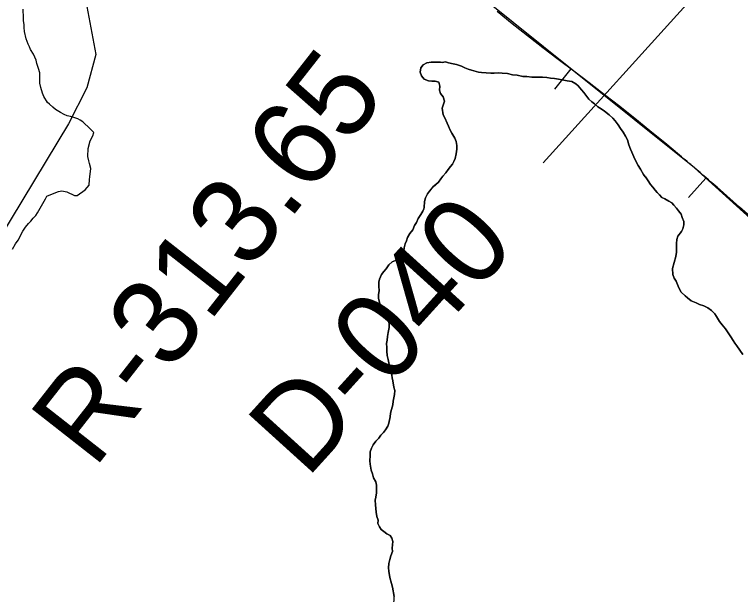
# Model space of a CAD drawing. Extents: x 3180038 to 3217926, y 922069 to 947485.
# Drawn here: x 3193903 to 3194600, y 943842 to 944398 of the extents above; entities that cross this region are included whole.
import ezdxf

# ---------------------------------------------------------------- set-up
doc = ezdxf.new("R2010")
doc.units = 0
for name, color, linetype in [('V-BORW-LINE', 7, 'Continuous'), ('V-RIVR-RANG', 7, 'Continuous'), ('V-RIVR-RANG-IDEN', 7, 'Continuous'), ('V-SITE-VEGE', 7, 'Continuous'), ('V-TOPO-SHOR', 7, 'Continuous')]:
    doc.layers.add(name, color=color, linetype=linetype)

msp = doc.modelspace()

# ---------------------------------------------------------------- linework, layer by layer
at = {"layer": 'V-BORW-LINE'}
for p, q in [((3194380.29, 944389.44), (3194365.84, 944401.34)), ((3194395.04, 944377.99), (3194380.29, 944389.44)), ((3194409.8, 944366.55), (3194395.04, 944377.99)), ((3194424.62, 944355.2), (3194409.8, 944366.55)), ((3194439.52, 944343.95), (3194424.62, 944355.2)), ((3194436.81, 944346.13), (3194421.11, 944326.68)), ((3194454.29, 944332.74), (3194439.52, 944343.95)), ((3194468.98, 944321.44), (3194454.29, 944332.74)), ((3194483.6, 944310.04), (3194468.98, 944321.44)), ((3194498.22, 944298.65), (3194483.6, 944310.04)), ((3194512.58, 944286.9), (3194498.22, 944298.65)), ((3194526.92, 944275.14), (3194512.58, 944286.9)), ((3194541.17, 944263.26), (3194526.92, 944275.14)), ((3194566.32, 944241.37), (3194549.54, 944222.84)), ((3194598.79, 944213.62), (3194577.15, 944232.55)), ((3194620.23, 944194.47), (3194598.79, 944213.62))]:
    msp.add_line(p, q, dxfattribs=at)
for points in [[(3194439.52, 944343.95), (3194323.17, 944437.85)], [(3194555.35, 944251.3), (3194439.52, 944343.95)], [(3194683.2, 944135.6), (3194555.35, 944251.3)]]:
    msp.add_lwpolyline(points, dxfattribs=at)
msp.add_spline([(3194577.15, 944232.55), (3194555.35, 944251.3), (3194541.17, 944263.26)], degree=3, dxfattribs=at)
at = {"layer": 'V-RIVR-RANG'}
msp.add_line((3194410.2, 944255.99), (3195228.69, 945160.69), dxfattribs=at)
at = {"layer": 'V-SITE-VEGE'}
for points in [[(3193978.81, 944285.29), (3193977.11, 944286.62), (3193973.73, 944290.17), (3193969.92, 944293.73), (3193968.22, 944295.5), (3193965.66, 944296.86), (3193963.52, 944298.21), (3193959.66, 944299.6), (3193956.22, 944300.54), (3193953.2, 944301.05), (3193950.2, 944302.42), (3193946.77, 944304.23), (3193942.08, 944307.37), (3193939.54, 944309.6), (3193936.14, 944312.28), (3193934.44, 944314.05), (3193930.68, 944319.77), (3193929.45, 944322.83), (3193927.85, 944328.5), (3193927.08, 944332.41), (3193926.79, 944338.48), (3193926.88, 944342.38), (3193925.68, 944346.74), (3193924.06, 944351.54), (3193923.27, 944354.59), (3193920.81, 944360.28), (3193917.88, 944364.68), (3193917.07, 944367.3), (3193915.83, 944369.92), (3193913.79, 944375.17), (3193912.22, 944382.14), (3193911.88, 944386.04), (3193911.94, 944388.64), (3193911.17, 944392.56), (3193911.23, 944395.15), (3193910.99, 944403.39)], [(3194309.19, 944352.77), (3194302.65, 944352.64), (3194298.37, 944351.89), (3194294.91, 944349.98), (3194292.85, 944347.18), (3194292.18, 944342.93), (3194293.24, 944339.49), (3194296.01, 944336.3), (3194299.95, 944334.79), (3194303.36, 944334.43), (3194306.49, 944334.35), (3194309.88, 944333.42), (3194310.93, 944329.7), (3194310.55, 944325.73), (3194311.61, 944322.57), (3194314.1, 944319.38), (3194315.43, 944315.37), (3194313.27, 944308.6), (3194314.26, 944302.03), (3194315.61, 944299.16), (3194318.06, 944294.27), (3194319.13, 944291.4), (3194320.74, 944287.38), (3194322.38, 944284.49), (3194325.39, 944279.59), (3194326.74, 944276.43), (3194327.22, 944272.72), (3194327.14, 944269.31), (3194326.75, 944264.77), (3194325.51, 944260.25), (3194324.3, 944257.43), (3194323.1, 944254.9), (3194323.1, 944254.62), (3194321.05, 944252.39), (3194319, 944249.59), (3194316.65, 944246.52), (3194313.73, 944243.18), (3194311.96, 944240.66), (3194309.62, 944237.59), (3194307, 944235.09), (3194304.38, 944232.87), (3194301.17, 944228.97), (3194299.11, 944226.17), (3194297.03, 944222.53), (3194296.38, 944218.84), (3194295.96, 944213.17), (3194295.65, 944212.04), (3194294.74, 944209.5), (3194292.67, 944206.42), (3194290.02, 944202.5), (3194288.51, 944198.84), (3194286.73, 944195.75), (3194284.93, 944191.81), (3194282.01, 944188.19), (3194279.92, 944184.25), (3194279, 944181.15), (3194277.79, 944178.33), (3194276.85, 944174.37), (3194276.49, 944171.25), (3194273.82, 944166.48), (3194271.21, 944164.26), (3194268.32, 944162.34), (3194265.16, 944161), (3194261.96, 944158.23), (3194259.31, 944154.31), (3194257.26, 944151.79), (3194254.92, 944148.72), (3194253.11, 944144.5), (3194252.47, 944141.39), (3194252.38, 944137.41), (3194252.57, 944133.42), (3194252.19, 944129.45), (3194252.1, 944125.75), (3194253.42, 944121.17), (3194255.04, 944117.72), (3194256.94, 944113.7), (3194259.72, 944111.07), (3194261.3, 944105.92), (3194262.34, 944101.62), (3194262.25, 944097.93), (3194261.29, 944093.12), (3194260.63, 944089.44), (3194260.26, 944085.75), (3194259.9, 944082.63), (3194260.1, 944078.93), (3194260.01, 944075.23), (3194260.48, 944070.96), (3194261.25, 944067.24), (3194262.27, 944062.38), (3194263.33, 944059.23), (3194264.65, 944054.65), (3194265.1, 944049.8), (3194265.88, 944046.66), (3194266.88, 944040.66), (3194267.66, 944037.51), (3194267.57, 944033.53), (3194266.64, 944030.43), (3194266, 944027.32), (3194265.92, 944023.91), (3194264.39, 944019.39), (3194263.73, 944015.71)], [(3194564.47, 944118.7), (3194560.24, 944120.22), (3194557.15, 944121.71), (3194552.36, 944123.53), (3194548.73, 944126.46), (3194546.5, 944128.5), (3194542.6, 944132.01), (3194540.42, 944136.04), (3194537.73, 944142.36), (3194535.81, 944145.25), (3194534.76, 944148.97), (3194534.32, 944154.67), (3194535.87, 944160.32), (3194537.44, 944166.26), (3194538.1, 944170.22), (3194538.21, 944175.05), (3194538.29, 944178.47), (3194538.38, 944182.44), (3194539.6, 944185.54), (3194542.83, 944190.02), (3194544.32, 944192.83), (3194545.26, 944196.5), (3194545.05, 944199.63), (3194543.72, 944203.65), (3194542.65, 944206.8), (3194540.17, 944209.99), (3194538.24, 944212.59), (3194535.75, 944215.49), (3194533.81, 944217.81), (3194530.72, 944219.31), (3194527.07, 944221.39), (3194523.98, 944222.88), (3194521.76, 944225.21), (3194519.54, 944227.53), (3194517.6, 944229.86), (3194515.4, 944232.75), (3194513.18, 944235.36), (3194510.99, 944238.83), (3194508.52, 944242.58), (3194507.95, 944242.59), (3194506.58, 944244.9), (3194503.57, 944250.09), (3194501.38, 944253.56), (3194499.47, 944257.01), (3194497.31, 944261.9), (3194495.14, 944266.22), (3194494.07, 944269.08), (3194492.46, 944273.39), (3194491.15, 944278.25), (3194489.25, 944281.71), (3194487.06, 944285.46), (3194484.3, 944288.94), (3194482.1, 944292.4), (3194479.35, 944296.45), (3194477.14, 944299.06), (3194473.52, 944302.27), (3194469.05, 944305.79), (3194465.97, 944307.85), (3194462.61, 944309.92), (3194459.54, 944312.55), (3194456.75, 944314.61), (3194453.96, 944317.23), (3194452.03, 944319.56), (3194449.28, 944323.6), (3194447.06, 944326.21), (3194443.74, 944329.99), (3194441.51, 944332.03), (3194437.58, 944334.11), (3194433.05, 944334.79), (3194428.24, 944335.76), (3194424.84, 944336.41), (3194421.16, 944337.06), (3194417.18, 944337.44), (3194413.79, 944338.08), (3194409.52, 944338.19), (3194404.41, 944338.31), (3194399.29, 944338.43), (3194394.47, 944338.82), (3194390.77, 944338.91), (3194385.11, 944340.18), (3194380.57, 944340.57), (3194376.05, 944341.82), (3194370.94, 944342.22), (3194367.53, 944342.3), (3194363.26, 944342.12), (3194359.85, 944342.2), (3194355.59, 944342.58), (3194351.05, 944342.69), (3194347.92, 944343.05), (3194341.43, 944344.9), (3194338.04, 944345.84), (3194334.94, 944347.33), (3194331.85, 944348.83), (3194327.05, 944350.36), (3194323.66, 944351.01), (3194319.41, 944351.96), (3194316.31, 944352.89), (3194313.17, 944352.39), (3194311.47, 944352.72), (3194310.05, 944352.75), (3194309.19, 944352.77)], [(3193900.82, 944173.21), (3193903.54, 944178.34), (3193906.21, 944181.74), (3193910.75, 944190.3), (3193913, 944194.15), (3193916.12, 944197.97), (3193918.34, 944200.08), (3193920.57, 944203.06), (3193923.23, 944205.6), (3193924.59, 944208.16), (3193932.27, 944221.41), (3193933.63, 944223.98), (3193940.62, 944226.85), (3193945, 944228.48), (3193948.04, 944229.27), (3193952.79, 944228.3), (3193960.06, 944224.66), (3193962.66, 944224.59), (3193970.59, 944230.04), (3193974.16, 944234.72), (3193974.71, 944239.91), (3193974.78, 944242.5), (3193975.83, 944250.71), (3193974.65, 944255.5), (3193973.84, 944258.12), (3193973.07, 944262.03), (3193973.25, 944269.82), (3193975.16, 944277.14), (3193977.87, 944281.84), (3193978.81, 944285.29)], [(3194601.77, 944072.03), (3194599.03, 944076.36), (3194595.99, 944080.42), (3194594.06, 944083.02), (3194592.42, 944085.62), (3194590.22, 944089.08), (3194587.2, 944093.71), (3194585.28, 944096.59), (3194581.96, 944100.65), (3194579.48, 944103.84), (3194576.46, 944108.46), (3194574.81, 944111.06), (3194571.76, 944114.26), (3194568.13, 944116.9), (3194564.47, 944118.7)], [(3194263.73, 944015.71), (3194263.37, 944012.31), (3194262.09, 944006.08), (3194260.88, 944003.26), (3194258.81, 943999.9), (3194256.76, 943997.1), (3194254.42, 943994.6), (3194252.37, 943991.8), (3194249.46, 943989.03), (3194246.81, 943985.39), (3194245.31, 943982.02), (3194244.09, 943978.63), (3194244.01, 943975.22), (3194243.89, 943970.1), (3194244.1, 943966.69), (3194245.1, 943960.98), (3194246.44, 943957.53), (3194247.21, 943953.82), (3194249.39, 943949.78), (3194250.17, 943946.64), (3194250.09, 943943.51), (3194250.28, 943939.24), (3194249.61, 943935.28), (3194248.97, 943932.16), (3194249.16, 943927.89), (3194249.85, 943920.77), (3194250.6, 943916.48), (3194251.65, 943913.04), (3194251.58, 943909.92), (3194252.93, 943906.76), (3194254.57, 943904.16), (3194257.08, 943902.11), (3194260.16, 943900.05), (3194263.25, 943898.27), (3194264.89, 943895.67), (3194265.67, 943892.52), (3194265.24, 943886.28), (3194265.5, 943883.13), (3194264.04, 943878.86), (3194262.87, 943875.15), (3194261.98, 943871.45), (3194261.67, 943867.45), (3194261.93, 943864.02), (3194263.02, 943858.02), (3194264.41, 943852.29), (3194265.52, 943848.85), (3194267.17, 943839.7)]]:
    msp.add_lwpolyline(points, dxfattribs=at)
at = {"layer": 'V-TOPO-SHOR'}
for points in [[(3194103.47, 945052.16), (3194084.52, 945015.47), (3194055.64, 944738.23), (3194035.42, 944674.69), (3194003.66, 944637.15), (3193980.55, 944559.18), (3193980.55, 944495.64), (3193974.78, 944452.32), (3193971.89, 944406.12), (3193980.55, 944359.91), (3193971.89, 944328.14), (3193954.56, 944293.49), (3193755.29, 943964.26), (3193718.66, 943910.51)], [(3194313.73, 944243.18), (3194316.65, 944246.52), (3194319, 944249.59), (3194321.05, 944252.39), (3194323.1, 944254.62), (3194323.1, 944254.9), (3194324.3, 944257.43), (3194325.51, 944260.25), (3194326.75, 944264.77), (3194327.14, 944269.31), (3194327.22, 944272.72), (3194326.74, 944276.43), (3194325.39, 944279.59), (3194322.38, 944284.49), (3194320.74, 944287.38), (3194319.13, 944291.4), (3194318.06, 944294.27), (3194315.61, 944299.16), (3194314.26, 944302.03), (3194313.27, 944308.6), (3194315.43, 944315.37), (3194314.1, 944319.38), (3194311.61, 944322.57), (3194310.55, 944325.73), (3194310.93, 944329.7), (3194309.88, 944333.42), (3194306.49, 944334.35), (3194303.36, 944334.42), (3194299.95, 944334.79), (3194296.01, 944336.3), (3194293.24, 944339.5), (3194292.18, 944342.93), (3194292.85, 944347.18), (3194294.91, 944349.98), (3194298.37, 944351.89), (3194302.65, 944352.64), (3194309.19, 944352.77), (3194310.05, 944352.75), (3194311.47, 944352.72), (3194313.17, 944352.39), (3194316.31, 944352.89), (3194319.41, 944351.96), (3194323.66, 944351.01), (3194327.05, 944350.36), (3194331.85, 944348.83), (3194334.94, 944347.33), (3194338.04, 944345.84), (3194341.43, 944344.9), (3194347.92, 944343.05), (3194351.05, 944342.69), (3194355.59, 944342.58), (3194359.85, 944342.2), (3194363.26, 944342.12), (3194367.53, 944342.3), (3194370.94, 944342.22), (3194376.05, 944341.82), (3194380.57, 944340.57), (3194385.11, 944340.18), (3194390.77, 944338.91), (3194394.47, 944338.82), (3194399.29, 944338.43), (3194404.41, 944338.31), (3194409.52, 944338.19), (3194413.79, 944338.08), (3194417.18, 944337.44), (3194421.16, 944337.06), (3194424.84, 944336.41), (3194428.24, 944335.76), (3194433.05, 944334.79), (3194437.58, 944334.11), (3194441.51, 944332.03), (3194443.74, 944329.99), (3194447.06, 944326.21), (3194449.28, 944323.6), (3194452.03, 944319.56), (3194453.96, 944317.23), (3194456.75, 944314.61), (3194459.54, 944312.55), (3194462.61, 944309.92), (3194465.97, 944307.85), (3194469.05, 944305.79), (3194473.52, 944302.27), (3194477.14, 944299.06), (3194479.35, 944296.45), (3194482.1, 944292.4), (3194484.3, 944288.94), (3194487.06, 944285.46), (3194489.25, 944281.71), (3194491.15, 944278.25), (3194492.46, 944273.39), (3194494.07, 944269.08), (3194495.14, 944266.22), (3194497.31, 944261.9), (3194499.47, 944257.01), (3194501.38, 944253.56), (3194503.57, 944250.09), (3194506.58, 944244.9), (3194507.95, 944242.59), (3194508.52, 944242.58), (3194510.99, 944238.83), (3194513.18, 944235.36)], [(3194265.24, 943886.28), (3194265.67, 943892.52), (3194264.89, 943895.67), (3194263.25, 943898.27), (3194260.16, 943900.05), (3194257.08, 943902.11), (3194254.57, 943904.16), (3194252.93, 943906.76), (3194251.58, 943909.92), (3194251.65, 943913.04), (3194250.6, 943916.48), (3194249.84, 943920.77), (3194249.16, 943927.89), (3194248.97, 943932.16), (3194249.61, 943935.28), (3194250.28, 943939.24), (3194250.09, 943943.51), (3194250.17, 943946.64), (3194249.39, 943949.78), (3194247.21, 943953.82), (3194246.44, 943957.53), (3194245.1, 943960.98), (3194244.1, 943966.69), (3194243.89, 943970.1), (3194244.01, 943975.22), (3194244.09, 943978.63), (3194245.31, 943982.02), (3194246.81, 943985.39), (3194249.46, 943989.03), (3194252.37, 943991.8), (3194254.42, 943994.6), (3194256.76, 943997.1), (3194258.81, 943999.9), (3194260.88, 944003.26), (3194262.09, 944006.08), (3194263.37, 944012.31), (3194263.73, 944015.71), (3194264.39, 944019.39), (3194265.92, 944023.91), (3194266, 944027.32), (3194266.64, 944030.43), (3194267.57, 944033.53), (3194267.66, 944037.51), (3194266.88, 944040.66), (3194265.88, 944046.66), (3194265.1, 944049.8), (3194264.65, 944054.65), (3194263.33, 944059.23), (3194262.27, 944062.38), (3194261.25, 944067.24), (3194260.48, 944070.96), (3194260.01, 944075.23), (3194260.1, 944078.93), (3194259.9, 944082.63), (3194260.26, 944085.75), (3194260.63, 944089.44), (3194261.29, 944093.12), (3194262.25, 944097.93), (3194262.34, 944101.62), (3194261.3, 944105.92), (3194259.72, 944111.07), (3194256.94, 944113.7), (3194255.04, 944117.72), (3194253.42, 944121.17), (3194252.1, 944125.75), (3194252.19, 944129.45), (3194252.57, 944133.42), (3194252.38, 944137.41), (3194252.47, 944141.39), (3194253.11, 944144.5), (3194254.92, 944148.72), (3194257.26, 944151.79), (3194259.31, 944154.31), (3194261.96, 944158.23), (3194265.16, 944161), (3194268.32, 944162.34), (3194271.21, 944164.26), (3194273.82, 944166.48), (3194276.49, 944171.25), (3194276.85, 944174.37), (3194277.79, 944178.33), (3194279, 944181.15), (3194279.92, 944184.25), (3194282.01, 944188.19), (3194284.93, 944191.81), (3194286.73, 944195.75), (3194288.51, 944198.84), (3194290.02, 944202.5), (3194292.67, 944206.42), (3194294.74, 944209.5), (3194295.65, 944212.04), (3194295.96, 944213.17), (3194296.38, 944218.84), (3194297.03, 944222.53), (3194299.11, 944226.17), (3194301.16, 944228.97), (3194304.39, 944232.87), (3194307, 944235.09), (3194309.62, 944237.59), (3194311.96, 944240.66), (3194313.73, 944243.18)], [(3194513.18, 944235.36), (3194515.4, 944232.75), (3194517.6, 944229.86), (3194519.54, 944227.53), (3194521.76, 944225.21), (3194523.98, 944222.88), (3194527.07, 944221.39), (3194530.72, 944219.31), (3194533.81, 944217.81), (3194535.75, 944215.49), (3194538.24, 944212.59), (3194540.17, 944209.99), (3194542.65, 944206.8), (3194543.72, 944203.65), (3194545.05, 944199.63), (3194545.26, 944196.5), (3194544.32, 944192.83), (3194542.83, 944190.02), (3194539.6, 944185.54), (3194538.38, 944182.44), (3194538.29, 944178.46), (3194538.21, 944175.05), (3194538.1, 944170.22), (3194537.44, 944166.26), (3194535.87, 944160.32), (3194534.32, 944154.67), (3194534.76, 944148.97), (3194535.81, 944145.25), (3194537.73, 944142.36), (3194540.42, 944136.04), (3194542.6, 944132.01), (3194546.5, 944128.5), (3194548.73, 944126.46), (3194552.36, 944123.53), (3194557.15, 944121.71), (3194560.24, 944120.22), (3194564.47, 944118.7), (3194568.13, 944116.9), (3194571.76, 944114.26), (3194574.81, 944111.06), (3194576.46, 944108.46), (3194579.48, 944103.84), (3194581.96, 944100.65), (3194585.28, 944096.59), (3194587.21, 944093.71), (3194590.22, 944089.08), (3194592.42, 944085.62), (3194594.06, 944083.02), (3194595.99, 944080.42), (3194599.03, 944076.36), (3194601.77, 944072.04)], [(3194293.07, 943790.36), (3194290.22, 943792.38), (3194284.25, 943795.57), (3194281.7, 943797.88), (3194278.86, 943800.76), (3194275.18, 943804.5), (3194273.2, 943807.37), (3194270.95, 943811.67), (3194268.97, 943814.83), (3194267.86, 943818.27), (3194267.6, 943821.7), (3194267.34, 943825.42), (3194266.81, 943830.56), (3194267.17, 943839.7), (3194265.52, 943848.85), (3194264.41, 943852.29), (3194263.03, 943858.02), (3194261.93, 943864.02), (3194261.67, 943867.45), (3194261.98, 943871.45), (3194262.87, 943875.15), (3194264.04, 943878.86), (3194265.5, 943883.13), (3194265.24, 943886.28)]]:
    msp.add_lwpolyline(points, dxfattribs=at)

# ---------------------------------------------------------------- texts
at = {"layer": 'V-RIVR-RANG-IDEN'}
for s, rotation, p in [('R-313.65', 51.91901, (3193979.07, 943961.36)), ('D-040', 47.81627, (3194182.96, 943952))]:
    msp.add_text(s, height=83, rotation=rotation, dxfattribs=at).set_placement(p)

doc.saveas('drawing.dxf')
